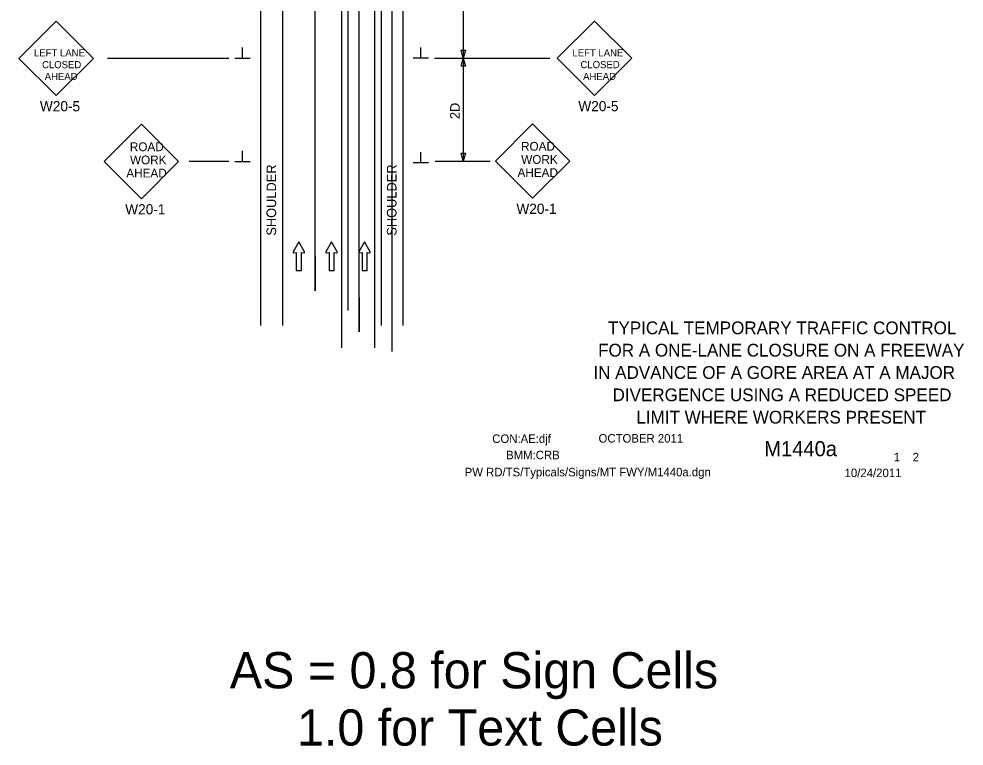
# Model space of a CAD drawing. Extents: x 16731 to 18464, y 5737 to 6974.
# Drawn here: x 16745 to 17435, y 5737 to 6268 of the extents above; entities that cross this region are included whole.
import ezdxf

# ---------------------------------------------------------------- set-up
doc = ezdxf.new("R2010")
doc.units = 0
for name, color, linetype in [('ALI_LEGAL_EX', 7, 'Continuous'), ('BORDER', 7, 'Continuous'), ('BORDER_SIGNAL_WO', 7, 'Continuous'), ('MT_SCRATCH_LEVEL_E', 7, 'Continuous'), ('PAVT_EDGE_EX', 7, 'Continuous'), ('TRAFFIC_SIGNS_PR', 7, 'Continuous'), ('TYPICAL_TEXT_DIMEN_PR', 7, 'Continuous')]:
    doc.layers.add(name, color=color, linetype=linetype)

msp = doc.modelspace()

# ---------------------------------------------------------------- linework, layer by layer
at = {"layer": 'ALI_LEGAL_EX'}
for p, q in [((16980.68, 6974.12), (16980.68, 6155.98)), ((17004.68, 6974.12), (17004.68, 6155.98)), ((16980.68, 6891.53), (16980.68, 6027.61)), ((17004.68, 6891.53), (17004.68, 6027.61)), ((16961.51, 6069.17), (16961.51, 6569.52)), ((16985.51, 6054.68), (16985.51, 6555.03)), ((16993.65, 6039.29), (16993.65, 6539.64)), ((17017.65, 6024.8), (17017.65, 6525.15))]:
    msp.add_line(p, q, dxfattribs=at)
for points in [[(16961.51, 6169.17), (16961.51, 6194.17)], [(16985.51, 6169.17), (16985.51, 6194.17)], [(16961.51, 6094.17), (16961.51, 6069.17)], [(16961.51, 6069.17), (16961.51, 6094.17)], [(16985.51, 6069.17), (16985.51, 6094.17)], [(16993.65, 6064.29), (16993.65, 6039.29)]]:
    msp.add_lwpolyline(points, dxfattribs=at)
at = {"layer": 'MT_SCRATCH_LEVEL_E'}
for p, q in [((16949.53, 6104.79), (16945.42, 6097.55)), ((16953.67, 6097.55), (16949.53, 6104.79)), ((16973.43, 6104.79), (16969.32, 6097.55)), ((16977.58, 6097.55), (16973.43, 6104.79)), ((16997.48, 6104.79), (16993.37, 6097.55)), ((17001.63, 6097.55), (16997.48, 6104.79)), ((16945.9, 6096.87), (16947.67, 6097.18)), ((16947.67, 6097.18), (16947.67, 6083.93)), ((16951.42, 6083.93), (16951.42, 6097.18)), ((16951.42, 6097.18), (16953.19, 6096.87)), ((16969.8, 6096.87), (16971.58, 6097.18)), ((16971.58, 6097.18), (16971.58, 6083.93)), ((16975.32, 6083.93), (16975.32, 6097.18)), ((16975.32, 6097.18), (16977.1, 6096.87)), ((16993.85, 6096.87), (16995.63, 6097.18)), ((16995.63, 6097.18), (16995.63, 6083.93)), ((16999.37, 6083.93), (16999.37, 6097.18)), ((16999.37, 6097.18), (17001.15, 6096.87)), ((16947.67, 6083.93), (16951.42, 6083.93)), ((16971.58, 6083.93), (16975.32, 6083.93)), ((16995.63, 6083.93), (16999.37, 6083.93))]:
    msp.add_line(p, q, dxfattribs=at)
for centre, start, end in [((16945.82, 6097.33), 150.42484, 279.96381), ((16953.26, 6097.33), 260.03619, 29.77312), ((16969.73, 6097.33), 150.42484, 279.96381), ((16977.17, 6097.33), 260.03619, 29.77312), ((16993.78, 6097.33), 150.42484, 279.96381), ((17001.22, 6097.33), 260.03619, 29.77312)]:
    msp.add_arc(centre, 0.463, start, end, dxfattribs=at)
at = {"layer": 'PAVT_EDGE_EX'}
for p, q in [((16921.51, 6569.52), (16921.51, 6043.9)), ((16937.51, 6569.52), (16937.51, 6043.9)), ((17009.51, 6569.52), (17009.51, 6043.9)), ((17025.51, 6569.52), (17025.51, 6043.9))]:
    msp.add_line(p, q, dxfattribs=at)
at = {"layer": 'TRAFFIC_SIGNS_PR'}
for p, q in [((16772.36, 6266), (16745.17, 6238.81)), ((16799.54, 6238.81), (16772.36, 6266)), ((17165.4, 6266.04), (17138.21, 6238.85)), ((17192.58, 6238.85), (17165.4, 6266.04)), ((16745.17, 6238.81), (16772.36, 6211.63)), ((16772.36, 6211.63), (16799.54, 6238.81)), ((17138.21, 6238.85), (17165.4, 6211.67)), ((17165.4, 6211.67), (17192.58, 6238.85)), ((16834.63, 6190.66), (16807.47, 6163.51)), ((16861.78, 6163.51), (16834.63, 6190.66)), ((17120.19, 6191.03), (17093.04, 6163.88)), ((17147.34, 6163.88), (17120.19, 6191.03)), ((16807.47, 6163.51), (16834.63, 6136.36)), ((16834.63, 6136.36), (16861.78, 6163.51)), ((17093.04, 6163.88), (17120.19, 6136.73)), ((17120.19, 6136.73), (17147.34, 6163.88))]:
    msp.add_line(p, q, dxfattribs=at)
at = {"layer": 'TYPICAL_TEXT_DIMEN_PR'}
for p, q in [((17069.51, 6313.85), (17069.51, 6238.85)), ((16908.39, 6238.85), (16908.39, 6246.64)), ((17038.64, 6238.85), (17038.64, 6246.64)), ((17069.51, 6238.85), (17067.94, 6244.72)), ((17067.94, 6244.72), (17069.51, 6244.72)), ((17069.51, 6244.72), (17071.08, 6244.72)), ((17071.08, 6244.72), (17069.51, 6238.85)), ((16809.96, 6238.85), (16898.51, 6238.85)), ((16902.76, 6238.85), (16914.01, 6238.85)), ((17044.26, 6238.85), (17033.01, 6238.85)), ((17048.51, 6238.85), (17132.62, 6238.85)), ((17067.94, 6232.99), (17069.51, 6238.85)), ((17069.51, 6238.85), (17069.51, 6163.85)), ((17069.51, 6238.85), (17071.08, 6232.99)), ((17069.51, 6232.99), (17067.94, 6232.99)), ((17071.08, 6232.99), (17069.51, 6232.99)), ((16908.39, 6163.41), (16908.39, 6171.19)), ((17038.64, 6162.64), (17038.64, 6170.42)), ((17069.51, 6163.85), (17067.94, 6169.72)), ((17067.94, 6169.72), (17069.51, 6169.72)), ((17069.51, 6169.72), (17071.08, 6169.72)), ((17071.08, 6169.72), (17069.51, 6163.85)), ((16898.51, 6163.41), (16869.5, 6163.41)), ((16902.76, 6163.41), (16914.01, 6163.41)), ((17044.26, 6162.64), (17033.01, 6162.64)), ((17049.01, 6163.85), (17089.16, 6163.85))]:
    msp.add_line(p, q, dxfattribs=at)

# ---------------------------------------------------------------- texts
at = {"layer": 'BORDER'}
for s, p in [('TYPICAL TEMPORARY TRAFFIC CONTROL', (17175.21, 6037.44)), ('FOR A ONE-LANE CLOSURE ON A FREEWAY', (17167.99, 6021.14)), ('IN ADVANCE OF A GORE AREA AT A MAJOR', (17164.54, 6004.84)), ('DIVERGENCE USING A REDUCED SPEED', (17178.52, 5988.54)), ('LIMIT WHERE WORKERS PRESENT', (17195.92, 5972.24))]:
    msp.add_text(s, height=9.3, dxfattribs=at).set_placement(p)
at = {"layer": 'BORDER_SIGNAL_WO'}
for s, height, p in [('CON:AE:djf  ', 6.2, (17090.69, 5958.06)), ('    OCTOBER 2011    ', 6.2, (17159.08, 5958.34)), ('    M1440a   ', 11, (17272.86, 5948.38)), ('BMM:CRB   ', 6.2, (17100.81, 5946.17)), (' 1    2 ', 6.2, (17381.45, 5944.7)), ('PW RD/TS/Typicals/Signs/MT FWY/M1440a.dgn      ', 6.2, (17070.55, 5933.71)), ('10/24/2011    ', 6.2, (17347.93, 5933.13)), ('AS = 0.8 for Sign Cells', 26.4241, (16899.12, 5778.94)), ('     1.0 for Text Cells', 26.4241, (16899.12, 5737.16))]:
    msp.add_text(s, height=height, dxfattribs=at).set_placement(p)
at = {"layer": 'TRAFFIC_SIGNS_PR'}
for s, height, p in [('LEFT LANE', 5.206, (16756.22, 6240.21)), ('LEFT LANE', 5.206, (17149.26, 6240.25)), ('CLOSED', 5.206, (16762.06, 6231.6)), ('CLOSED', 5.206, (17155.1, 6231.64)), ('AHEAD', 5.206, (16764.01, 6222.99)), ('AHEAD', 5.206, (17157.04, 6223.03)), ('W20-5', 7.449, (16760.52, 6200.17)), ('W20-5', 7.449, (17153.55, 6200.21)), ('ROAD', 6.4, (16826.17, 6171.05)), ('ROAD', 6.4, (17111.73, 6171.41)), ('WORK', 6.4, (16826.28, 6161.45)), ('WORK', 6.4, (17111.84, 6161.81)), ('AHEAD', 6.4, (16823.59, 6151.85)), ('AHEAD', 6.4, (17109.15, 6152.21)), ('W20-1', 7.44, (16822.8, 6124.92)), ('W20-1', 7.44, (17108.36, 6125.29))]:
    msp.add_text(s, height=height, dxfattribs=at).set_placement(p)
at = {"layer": 'TYPICAL_TEXT_DIMEN_PR'}
for s, p in [('2D', (17066.95, 6194.43)), ('SHOULDER', (16932.95, 6109.34)), ('SHOULDER', (17020.81, 6109.34))]:
    msp.add_text(s, height=7, rotation=90, dxfattribs=at).set_placement(p)

doc.saveas('drawing.dxf')
